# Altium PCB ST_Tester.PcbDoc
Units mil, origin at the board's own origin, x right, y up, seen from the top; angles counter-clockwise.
Board outline 3800 x 2200 mil, 2 copper layers (Top Layer, Bottom Layer); 29 components, 25 nets, 113 pads, 0 vias.
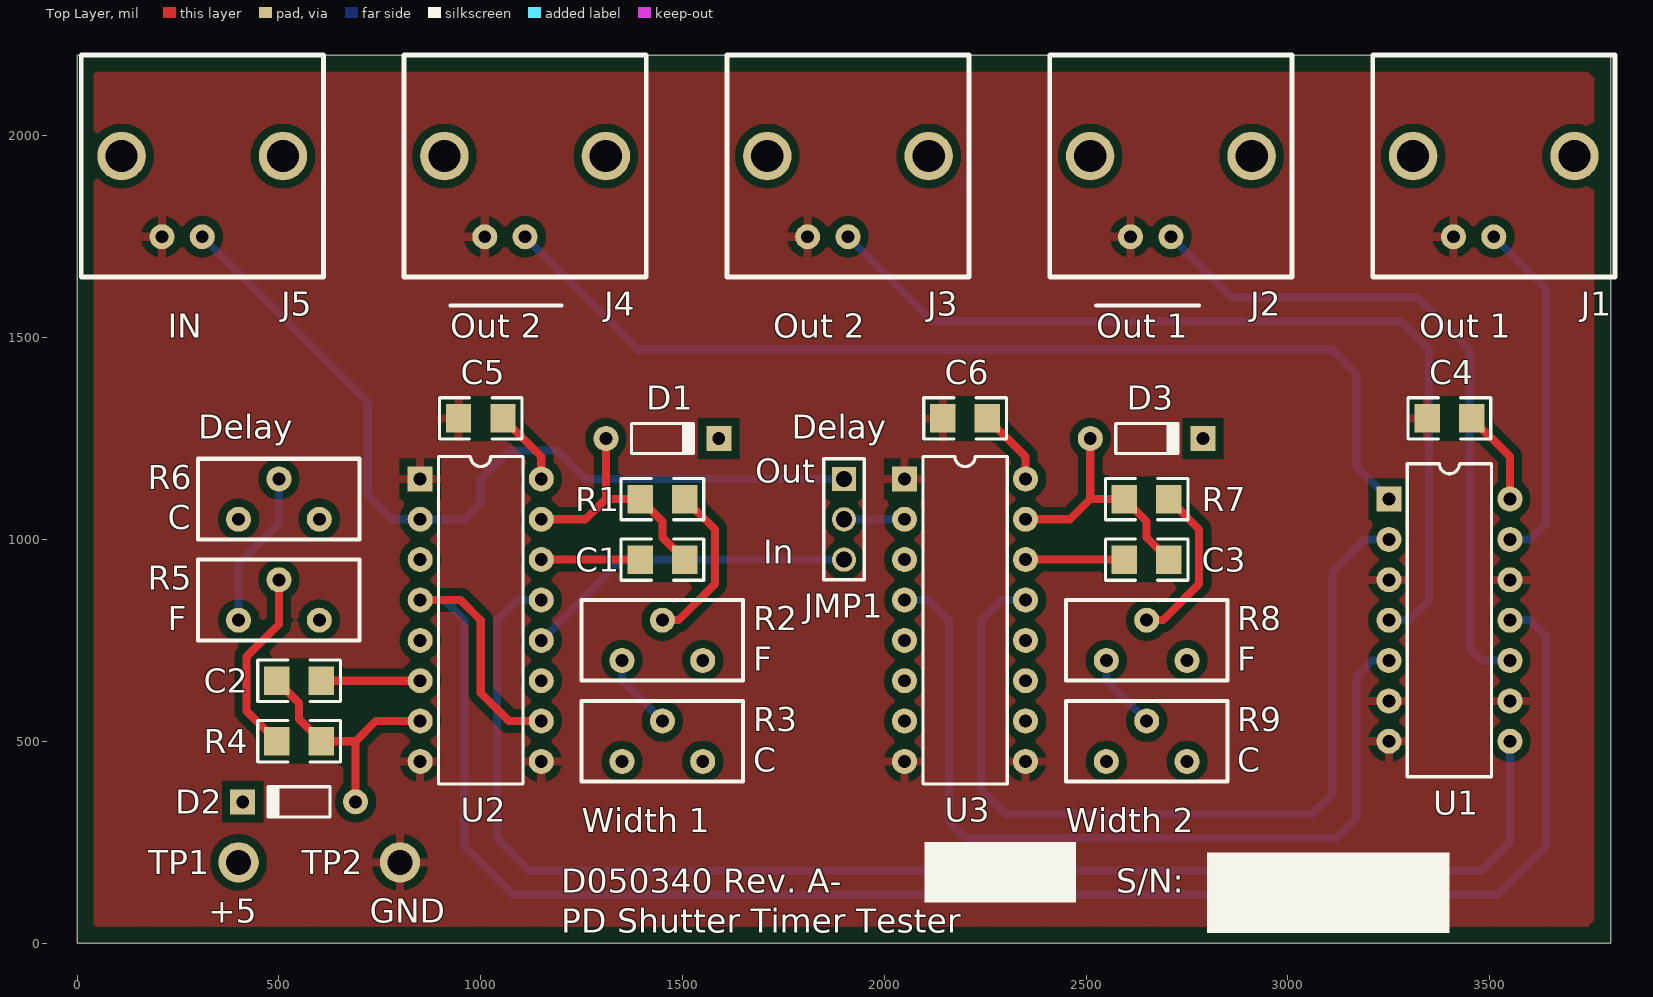
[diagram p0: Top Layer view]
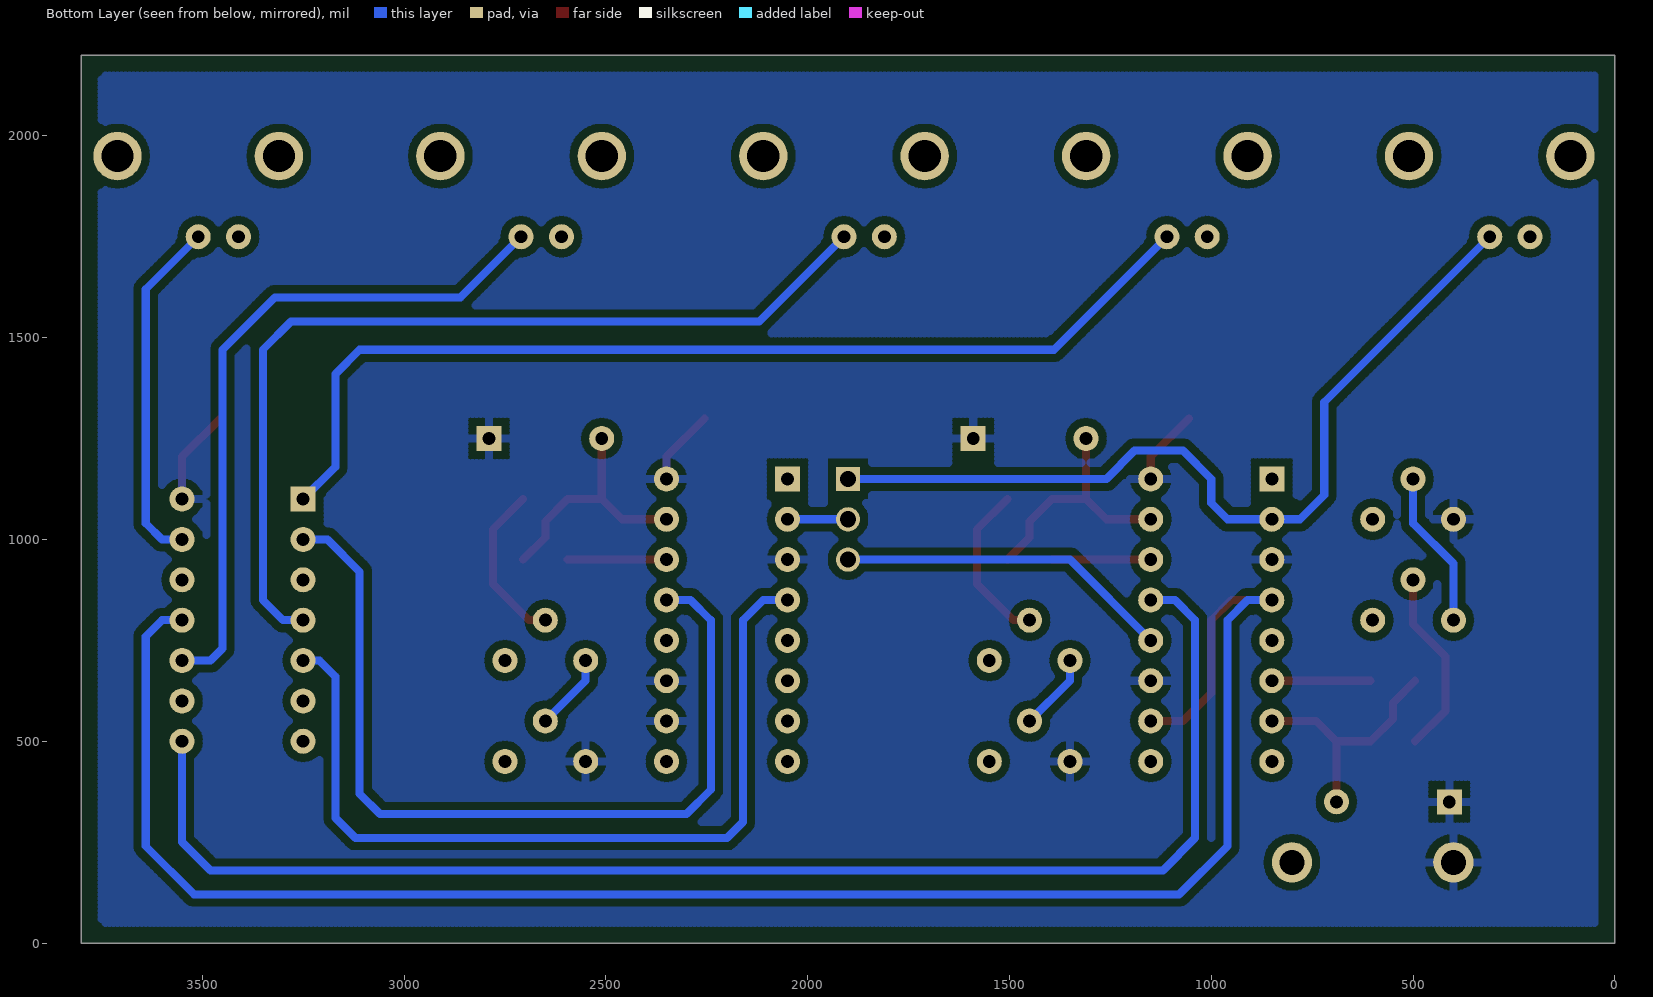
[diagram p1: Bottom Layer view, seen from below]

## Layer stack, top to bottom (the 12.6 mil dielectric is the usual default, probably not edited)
Top Layer: signal copper 1.4
Dielectric: dielectric 12.6, FR-4, Dk 4.8
Bottom Layer: signal copper 1.4

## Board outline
0,0 3800,0 3800,2200 0,2200

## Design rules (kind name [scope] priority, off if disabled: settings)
Clearance Clearance_1 [InPoly] p1: gap=20
Clearance [All] p2: gap=20
ComponentClearance [All] p1 off: gap=10 collisioncheckmode=0
FanoutControl Fanout_BGA [IsBGA] p1 off: bgadir=Out bgaviamode=Centered fanoutstyle=Auto fanoutdirection=Alternating viagrid=1 // Fanout_BGA (Default Rule)
FanoutControl Fanout_LCC [IsLCC] p2 off: bgadir=Out bgaviamode=Centered fanoutstyle=Auto fanoutdirection=Alternating viagrid=1 // Fanout_LCC (Default Rule)
FanoutControl Fanout_SOIC [IsSOIC] p3 off: bgadir=Out bgaviamode=Centered fanoutstyle=Auto fanoutdirection=Alternating viagrid=1 // Fanout_SOIC (Default Rule)
FanoutControl Fanout_Small [(CompPinCount < 5)] p4 off: bgadir=Out bgaviamode=Centered fanoutstyle=Auto fanoutdirection=OutThenIn viagrid=1 // Fanout_Small (Default Rule)
FanoutControl Fanout_Default [All] p5 off: bgadir=Out bgaviamode=Centered fanoutstyle=Auto fanoutdirection=Alternating viagrid=1 // Fanout_Default (Default Rule)
Height [All] p1 off: minheight=0 maxheight=1000 prefheight=500
HoleSize [All] p1 off: absolutevalues=TRUE maxlimit=100 minlimit=1 maxpercent=80.000 minpercent=20.000
LayerPairs [All] p1 off: enforce=TRUE
PasteMaskExpansion [All] p1 off: expansion=0
PolygonConnect [All] p1: connectstyle=Relief reliefconductorwidth=20 reliefentries=4 polygonreliefangle="90 Angle"
RoomDefinition ST_Tester [InComponentClass('ST_Tester')] p1 off: confinementstyle=ConfineOut formatcopy=TRUE lockcomponents=FALSE outline 0,2200 0,2700 500,2700 500,2200
RoutingVias [All] p1: holewidth=40 width=80 viastyle="Through Hole" minholewidth=40 minwidth=80 maxholewidth=40 maxwidth=80
SolderMaskExpansion [All] p1 off: expansion=4
TestPointUsage [All] p1: valid=0 allowmultiple=FALSE
Testpoint [All] p1: side=15 testpointundercomponent=TRUE minsize=40 maxsize=100 preferedsize=60 minholesize=0 maxholesize=40 preferedholesize=32 testpointgrid=1 style=1023 order=0-112345678
Width [All] p1: maxlimit=100 minlimit=10 preferedwidth=10 toplayer_prefwidth=20 bottomlayer_prefwidth=20 minimp=50.000000 maximp=50.000000 favimp=50.000000
8 further rules are at their usual default settings.

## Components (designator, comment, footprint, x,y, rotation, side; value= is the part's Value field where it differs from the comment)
C1 "10nF" CR3216-1206 1450,950 r0 top
C2 "10nF" CR3216-1206 550,650 r180 top
C3 "10nF" CR3216-1206 2650,950 r0 top
C4 "1uF" CR3216-1206 3400,1300 r0 top
C5 "1uF" CR3216-1206 1000,1300 r0 top
C6 "1uF" CR3216-1206 2200,1300 r0 top
D1 "Diode 1N4148" DIO7.1-3.9x1.9 1450,1250 r0 top
D2 "Diode 1N4148" DIO7.1-3.9x1.9 550,350 r180 top
D3 "Diode 1N4148" DIO7.1-3.9x1.9 2650,1250 r0 top
J1 "BNC" BNC1 3200,1650 r0 top
J2 "BNC" BNC1 2400,1650 r0 top
J3 "BNC" BNC1 1600,1650 r0 top
J4 "BNC" BNC1 800,1650 r0 top
J5 "BNC" BNC1 0,1650 r0 top
JMP1 "JMPR3" hdr1x3 1900,1150 r270 top
R1 "1k" CR3216-1206 1450,1100 r0 top
R2 "RPot" "POT, VERT" 1450,750 r180 top
R3 "RPot" "POT, VERT" 1450,500 r180 top
R4 "1k" CR3216-1206 550,500 r180 top
R5 "RPot" "POT, VERT" 500,850 r180 top
R6 "RPot" "POT, VERT" 500,1100 r180 top
R7 "1k" CR3216-1206 2650,1100 r0 top
R8 "RPot" "POT, VERT" 2650,750 r180 top
R9 "RPot" "POT, VERT" 2650,500 r180 top
TP1 "TP" TP1 400,200 r0 top
TP2 "TP" TP1 800,200 r0 top
U1 "SN74HC02N" N014 3400,800 r270 top
U2 "74HC123E" DIP-16 1000,800 r270 top
U3 "74HC123E" DIP-16 2200,800 r270 top

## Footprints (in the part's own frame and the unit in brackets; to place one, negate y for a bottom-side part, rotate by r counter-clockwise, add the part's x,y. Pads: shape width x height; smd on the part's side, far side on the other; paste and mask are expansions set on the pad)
BNC1 [mil]
  round 62 hole 32: 1(310,100) 2(210,100)
  round 120 hole 80: 3(110,300) 4(510,300)
  silkscreen extent 10,0 610,550
CR3216-1206 [mm]
  rect 1.6x1.8 smd: 1(-1.4,0) 2(1.4,0)
  silkscreen extent -2.6,-1.3 2.6,1.3
DIO7.1-3.9x1.9 [mil]
  round 62 hole 32: 1(-139.76,0)
  rect 62x62 hole 32: 2(139.76,0)
  silkscreen extent -77,-37 81,37
DIP-16 [mil]
  rect 62x62 hole 32: 1(-350,-150)
  round 62 hole 32: 2(-250,-150) 3(-150,-150) 4(-50,-150) 5(50,-150) 6(150,-150) 7(250,-150) 8(350,-150) 9(350,150) 10(250,150) 11(150,150) 12(50,150) 13(-50,150) 14(-150,150) 15(-250,150) 16(-350,150)
  silkscreen extent -406,-104 406,104
hdr1x3 [mil] "Connector; Header; 3 Position"
  rect 60x60 hole 40: 1(0,0)
  round 60 hole 40: 2(100,0) 3(200,0)
  silkscreen extent -50,-50 250,50
N014 [mil] "DIP; 14 Leads; Row Spacing 7.62 mm; Pitch 2.54 mm"
  rect 62x62 hole 32: 1(-300,-150)
  round 62 hole 32: 2(-200,-150) 3(-100,-150) 4(0,-150) 5(100,-150) 6(200,-150) 7(300,-150) 8(300,150) 9(200,150) 10(100,150) 11(0,150) 12(-100,150) 13(-200,150) 14(-300,150)
  silkscreen extent -388,-104 388,104
"POT, VERT" [mil]
  round 62 hole 32: 1(-100,50) 2(100,50) 3(0,-50)
  silkscreen extent -200,-100 200,100
TP1 [mil]
  round 100 hole 62: 1(0,0)

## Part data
C1 C2 C3 C4 C5 C6: library part "Cap Semi", "Capacitor (Semiconductor SIM Model)"
D1 D2 D3: "High Conductance Fast Diode"
J1 J2 J3 J4 J5: "BNC Elbow Connector"
R1 R4 R7: library part Res1, "Resistor"
R2 R3 R5 R6 R8 R9: "Potentiometer"
U1: "Quadruple 2-Input Positive-NOR Gate"
U2 U3: library part SN74LS123D, "Retriggerable Monostable Multivibrator"

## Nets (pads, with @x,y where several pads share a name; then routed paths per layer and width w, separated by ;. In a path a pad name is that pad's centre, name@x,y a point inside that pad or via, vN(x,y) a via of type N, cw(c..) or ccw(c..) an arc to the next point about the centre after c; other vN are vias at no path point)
GND: C4.1 C5.1 C6.1 J1.2 J2.2 J3.2 J4.2 J5.2 TP2.1 U1.3 U1.6 U1.7 U1.9 U1.12 U2.1 U2.8 U2.9 U3.1 U3.8 U3.9
NetC1_1: C1.1 U2.14 | length 244.9
  Top Layer w20: U2.14 C1.1
NetC1_2: C1.2 D1.1 R1.1 U2.15 | length 610.9
  Top Layer w20: U2.15 1260,1050 1310.24,1100.24 D1.1 ; 1310.47,1100 R1.1 1450,1044.88 1450,1005.12 C1.2
NetC2_1: C2.1 U2.6 | length 244.9
  Top Layer w20: C2.1 U2.6
NetC2_2: C2.2 D2.1 R4.1 U2.7 | length 611.2
  Top Layer w20: C2.2 550,594.88 550,555.12 R4.1 689.53,500 689.76,499.76 ; D2.1 689.76,499.76 ; U2.7 740,550 689.76,499.76
NetC3_1: C3.1 U3.14 | length 244.9
  Top Layer w20: U3.14 C3.1
NetC3_2: C3.2 D3.1 R7.1 U3.15 | length 610.9
  Top Layer w20: U3.15 2460,1050 2510.24,1100.24 D3.1 ; 2510.47,1100 R7.1 2650,1044.88 2650,1005.12 C3.2
NetJ1_1: J1.1 U1.13 | length 870.4
  Bottom Layer w20: J1.1 3640,1620 3640,1040 3600,1000 U1.13
NetJ2_1: J2.1 U1.10 | length 1708.4
  Bottom Layer w20: J2.1 2860,1600 3320,1600 3450,1470 3450,730 3480,700 U1.10
NetJ3_1: J3.1 U1.4 | length 2296.7
  Bottom Layer w20: J3.1 2120,1540 3280,1540 3350,1470 3350,850 3300,800 U1.4
NetJ4_1: J4.1 U1.1 | length 2544
  Bottom Layer w20: J4.1 1390,1470 3110,1470 3170,1410 3170,1180 U1.1
NetJ5_1: J5.1 JMP1.1 U2.2 | length 2149.2
  Bottom Layer w20: J5.1 720,1340 720,1110 780,1050 960,1050 1000,1090 1000,1150 1070,1220 1190,1220 1260,1150 JMP1.1
NetJMP1_2: JMP1.2 U3.2 | length 150
  Bottom Layer w20: JMP1.2 U3.2
NetJMP1_3: JMP1.3 U2.12 | length 832.8
  Bottom Layer w20: U2.12 1350,950 JMP1.3
NetR1_2: R1.2 R2.3 | length 408.3
  Top Layer w20: R2.3 1490,800 1580,890 1580,1025.12 R1.2
NetR2_2: R2.2 R3.3 | length 191.4
  Bottom Layer w20: R2.2 1350,650 R3.3
NetR4_2: R4.2 R5.3 | length 464.2
  Top Layer w20: R4.2 420,574.88 420,710 500,790 R5.3
NetR5_2: R5.2 R6.3 | length 391.4
  Bottom Layer w20: R5.2 400,940 500,1040 R6.3
NetR7_2: R7.2 R8.3 | length 408.3
  Top Layer w20: R8.3 2690,800 2780,890 2780,1025.12 R7.2
NetR8_2: R8.2 R9.3 | length 191.4
  Bottom Layer w20: R8.2 2550,650 R9.3
NetU1_2: U1.2 U3.13 | length 2189.4
  Bottom Layer w20: U3.13 2290,850 2240,800 2240,380 2300,320 3060,320 3110,370 3110,920 3190,1000 U1.2
NetU1_5: U1.5 U3.4 | length 2124.6
  Bottom Layer w20: U3.4 2110,850 2160,800 2160,300 2200,260 3120,260 3170,310 3170,660 3210,700 U1.5
NetU1_8: U1.8 U2.13 | length 3492.8
  Bottom Layer w20: U2.13 1090,850 1040,800 1040,260 1120,180 3480,180 3550,250 U1.8
NetU1_11: U1.11 U2.4 U2.10 | length 4626.4
  Top Layer w20: U2.4 950,850 1000,800 1000,620 1070,550 U2.10
  Bottom Layer w20: U2.4 910,850 960,800 960,240 1080,120 3520,120 3640,240 3640,760 3600,800 U1.11
VCC: C4.2 C5.2 C6.2 D1.2 D2.2 D3.2 R3.2 R6.2 R9.2 TP1.1 U1.14 U2.3 U2.11 U2.16 U3.3 U3.10 U3.11 U3.16 | length 617.9
  Top Layer w20: C5.2 1150,1205.12 U2.16 ; C6.2 2350,1205.12 U3.16 ; C4.2 3550,1205.12 U1.14
pads on no net: J1.3 J1.4 J2.3 J2.4 J3.3 J3.4 J4.3 J4.4 J5.3 J5.4 R2.1 R3.1 R5.1 R6.1 R8.1 R9.1 U2.5 U3.5 U3.6 U3.7 U3.12

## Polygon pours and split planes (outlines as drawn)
GND on Top Layer (hatched 90Degree grid 10 track 20, remove dead copper): 3750,50 3750,2150 50,2150 50,50
VCC on Bottom Layer (hatched 90Degree grid 10 track 20, remove dead copper): 3750,50 3750,2150 50,2150 50,50

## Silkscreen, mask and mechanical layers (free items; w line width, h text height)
Top Overlay:
  rectangle: 2800,25 3400,225
  rectangle: 2100,100 2475,250
  lines w10: 925,1580 1200,1580 ; 2525,1580 2780,1580
  text "IN" at 225,1500 h60
  text "Out 2" at 925,1500 h60
  text "Out 2" at 1725,1500 h60
  text "Out 1" at 2525,1500 h60
  text "Out 1" at 3325,1500 h60
  text "Delay" at 300,1250 h60
  text "Delay" at 1770,1250 h60
  text "Out" at 1680,1140 h60
  text "C" at 225,1025 h60
  text "In" at 1700,940 h60
  text "F" at 225,775 h60
  text "F" at 1675,675 h60
  text "F" at 2875,675 h60
  text "C" at 1675,425 h60
  text "C" at 2875,425 h60
  text "Width 1" at 1250,275 h60
  text "Width 2" at 2450,275 h60
  text "D050340 Rev. A-" at 1200,125 h60
  text "S/N:" at 2575,125 h60
  text "+5" at 325,50 h60
  text "GND" at 725,50 h60
  text "PD Shutter Timer Tester" at 1200,25 h60
Mechanical 1:
  the board outline again, w10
